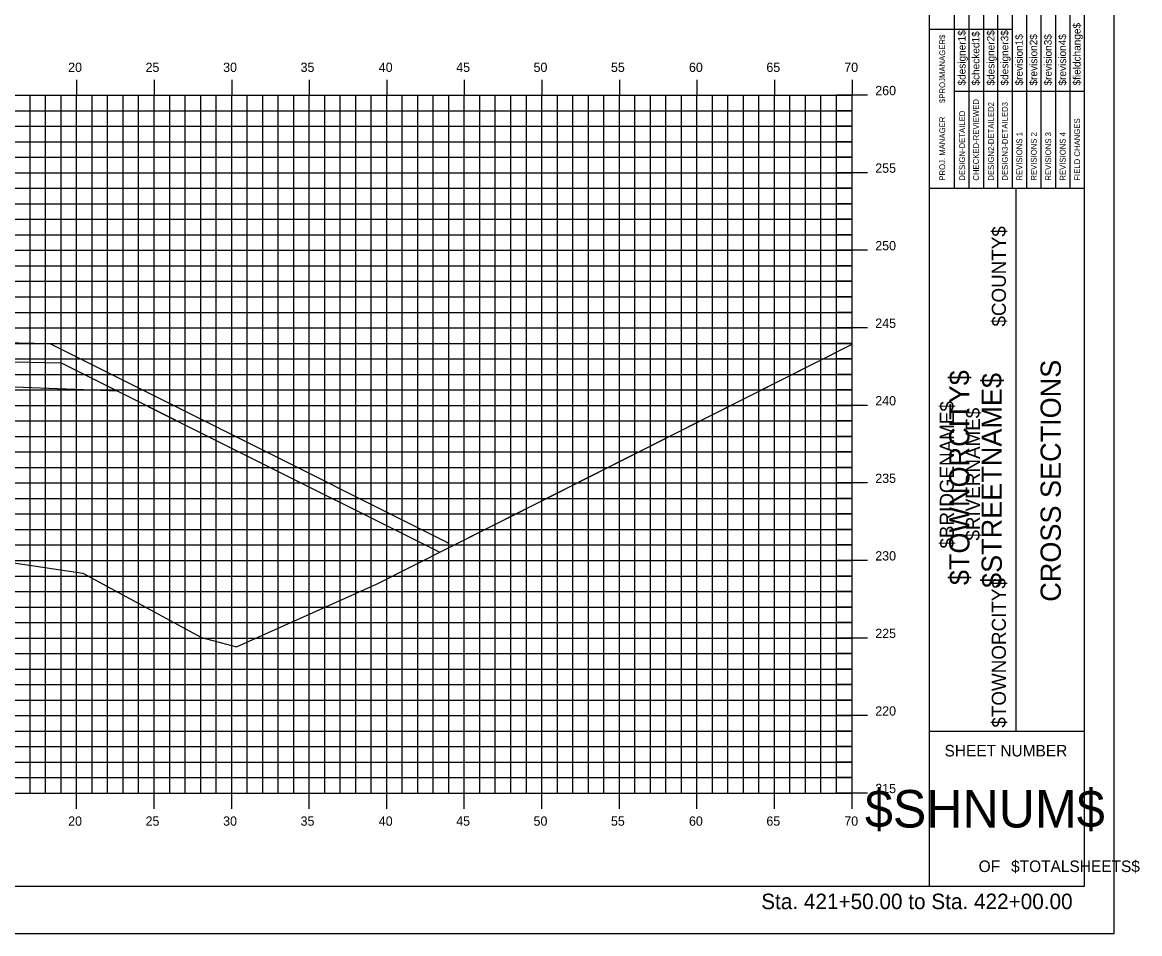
# Model space of a CAD drawing. Extents: x 1168600 to 1177589, y 610178 to 611246.
# Drawn here: x 1174314.9 to 1174386.9, y 610900.5 to 610959.3 of the extents above; entities that cross this region are included whole.
import ezdxf

# ---------------------------------------------------------------- set-up
doc = ezdxf.new("R2010")
doc.units = 0
for name, color, linetype in [('_Construction', 7, 'Continuous'), ('_Station Equation', 7, 'Continuous'), ('D_Roadway_SubGrade', 7, 'Continuous'), ('D_Slope_Direction', 7, 'Continuous'), ('D_Text_Standard', 7, 'Continuous'), ('H_V ANNOTATION', 7, 'Continuous'), ('MAJOR', 7, 'Continuous'), ('MINOR', 7, 'Continuous')]:
    doc.layers.add(name, color=color, linetype=linetype)

msp = doc.modelspace()

# ---------------------------------------------------------------- linework, layer by layer
at = {"layer": '_Construction'}
for p, q in [((1174373.367, 610903.599), (1174373.367, 611008.599)), ((1174383.367, 610903.599), (1174383.367, 611008.599)), ((1174373.367, 610948.599), (1174383.367, 610948.599)), ((1174378.958, 610913.599), (1174378.958, 610948.599)), ((1174373.367, 610913.599), (1174383.367, 610913.599)), ((1174223.367, 610903.596), (1174383.367, 610903.596))]:
    msp.add_line(p, q, dxfattribs=at)
msp.add_lwpolyline([(1174215.274, 610900.537), (1174385.274, 610900.537), (1174385.274, 611010.537), (1174215.274, 611010.537)], close=True, dxfattribs=at)
for points in [[(1174375.915, 610948.602), (1174375.915, 610966.099)], [(1174376.846, 610966.099), (1174376.846, 610948.602)], [(1174377.778, 610948.602), (1174377.778, 610966.099)], [(1174378.71, 610948.602), (1174378.71, 610966.099)], [(1174379.641, 610948.602), (1174379.641, 610966.099)], [(1174380.573, 610948.602), (1174380.573, 610966.099)], [(1174381.505, 610948.602), (1174381.505, 610966.099)], [(1174382.437, 610948.602), (1174382.437, 610966.099)], [(1174374.983, 610948.602), (1174374.983, 610965.393)], [(1174373.367, 610958.849), (1174374.983, 610958.849)], [(1174374.982, 610958.849), (1174378.709, 610958.849)], [(1174374.982, 610954.849), (1174383.367, 610954.849)]]:
    msp.add_lwpolyline(points, dxfattribs=at)
at = {"layer": '_Station Equation'}
for points in [[(1174228.367, 610948.347), (1174246.198, 610940.577), (1174261.693, 610933.725), (1174264.668, 610933.087), (1174297.116, 610927.92), (1174312.267, 610924.748), (1174318.764, 610923.769), (1174326.425, 610919.637), (1174328.67, 610919.022), (1174337.751, 610923.098), (1174368.367, 610938.545)], [(1174313.66, 610938.66), (1174316.63, 610938.598), (1174319.27, 610937.276), (1174319.309, 610937.257), (1174327.558, 610933.126), (1174327.716, 610933.047), (1174327.778, 610933.016), (1174342.333, 610925.727), (1174342.336, 610925.696), (1174342.337, 610925.757), (1174342.337, 610925.784), (1174342.341, 610925.413), (1174342.341, 610925.414), (1174342.381, 610925.434), (1174342.384, 610925.436), (1174348.791, 610928.668), (1174368.367, 610938.545)]]:
    msp.add_lwpolyline(points, dxfattribs=at)
at = {"layer": 'D_Roadway_SubGrade'}
msp.add_lwpolyline([(1174314.367, 610937.396), (1174317.367, 610937.336), (1174321.03, 610935.504), (1174314.367, 610935.771)], close=True, dxfattribs=at)
at = {"layer": 'D_Slope_Direction'}
for points in [[(1174317.367, 610937.336), (1174328.45, 610931.794)], [(1174328.45, 610931.794), (1174341.778, 610925.13)]]:
    msp.add_lwpolyline(points, dxfattribs=at)
at = {"layer": 'D_Text_Standard'}
msp.add_lwpolyline([(1174267.429, 610932.647), (1174268.284, 610933.074), (1174276.691, 610937.278), (1174279.367, 610938.616), (1174282.367, 610938.676), (1174298.367, 610938.036), (1174314.367, 610937.396), (1174317.367, 610937.336), (1174321.03, 610935.504), (1174328.45, 610931.794), (1174341.778, 610925.13)], dxfattribs=at)
at = {"layer": 'MAJOR'}
for p, q in [((1174318.367, 610955.598), (1174318.367, 610954.596)), ((1174323.367, 610955.598), (1174323.367, 610954.596)), ((1174328.367, 610955.598), (1174328.367, 610954.596)), ((1174333.367, 610955.598), (1174333.367, 610954.596)), ((1174338.367, 610955.598), (1174338.367, 610954.596)), ((1174343.367, 610955.598), (1174343.367, 610954.596)), ((1174348.367, 610955.598), (1174348.367, 610954.596)), ((1174353.367, 610955.598), (1174353.367, 610954.596)), ((1174358.367, 610955.598), (1174358.367, 610954.596)), ((1174363.367, 610955.598), (1174363.367, 610954.596)), ((1174368.367, 610955.598), (1174368.367, 610954.596)), ((1174228.367, 610954.596), (1174368.367, 610954.596)), ((1174228.367, 610954.596), (1174368.367, 610954.596)), ((1174318.367, 610909.596), (1174318.367, 610954.596)), ((1174323.367, 610909.596), (1174323.367, 610954.596)), ((1174328.367, 610909.596), (1174328.367, 610954.596)), ((1174333.367, 610909.596), (1174333.367, 610954.596)), ((1174338.367, 610909.596), (1174338.367, 610954.596)), ((1174343.367, 610909.596), (1174343.367, 610954.596)), ((1174348.367, 610909.596), (1174348.367, 610954.596)), ((1174353.367, 610909.596), (1174353.367, 610954.596)), ((1174358.367, 610909.596), (1174358.367, 610954.596)), ((1174363.367, 610909.596), (1174363.367, 610954.596)), ((1174369.369, 610954.596), (1174367.365, 610954.596)), ((1174368.367, 610909.596), (1174368.367, 610954.596)), ((1174368.367, 610909.596), (1174368.367, 610954.596)), ((1174228.367, 610949.596), (1174368.367, 610949.596)), ((1174369.369, 610949.596), (1174367.365, 610949.596)), ((1174228.367, 610944.596), (1174368.367, 610944.596)), ((1174369.369, 610944.596), (1174367.365, 610944.596)), ((1174228.367, 610939.596), (1174368.367, 610939.596)), ((1174369.369, 610939.596), (1174367.365, 610939.596)), ((1174228.367, 610934.596), (1174368.367, 610934.596)), ((1174369.369, 610934.596), (1174367.365, 610934.596)), ((1174228.367, 610929.596), (1174368.367, 610929.596)), ((1174369.369, 610929.596), (1174367.365, 610929.596)), ((1174228.367, 610924.596), (1174368.367, 610924.596)), ((1174369.369, 610924.596), (1174367.365, 610924.596)), ((1174228.367, 610919.596), (1174368.367, 610919.596)), ((1174369.369, 610919.596), (1174367.365, 610919.596)), ((1174228.367, 610914.596), (1174368.367, 610914.596)), ((1174369.369, 610914.596), (1174367.365, 610914.596)), ((1174228.367, 610909.596), (1174368.367, 610909.596)), ((1174228.367, 610909.596), (1174368.367, 610909.596)), ((1174318.367, 610908.594), (1174318.367, 610909.596)), ((1174323.367, 610908.594), (1174323.367, 610909.596)), ((1174328.367, 610908.594), (1174328.367, 610909.596)), ((1174333.367, 610908.594), (1174333.367, 610909.596)), ((1174338.367, 610908.594), (1174338.367, 610909.596)), ((1174343.367, 610908.594), (1174343.367, 610909.596)), ((1174348.367, 610908.594), (1174348.367, 610909.596)), ((1174353.367, 610908.594), (1174353.367, 610909.596)), ((1174358.367, 610908.594), (1174358.367, 610909.596)), ((1174363.367, 610908.594), (1174363.367, 610909.596)), ((1174369.369, 610909.596), (1174367.365, 610909.596)), ((1174368.367, 610908.594), (1174368.367, 610909.596))]:
    msp.add_line(p, q, dxfattribs=at)
at = {"layer": 'MINOR'}
for p, q in [((1174315.367, 610909.596), (1174315.367, 610954.596)), ((1174316.367, 610909.596), (1174316.367, 610954.596)), ((1174317.367, 610909.596), (1174317.367, 610954.596)), ((1174319.367, 610909.596), (1174319.367, 610954.596)), ((1174320.367, 610909.596), (1174320.367, 610954.596)), ((1174321.367, 610909.596), (1174321.367, 610954.596)), ((1174322.367, 610909.596), (1174322.367, 610954.596)), ((1174324.367, 610909.596), (1174324.367, 610954.596)), ((1174325.367, 610909.596), (1174325.367, 610954.596)), ((1174326.367, 610909.596), (1174326.367, 610954.596)), ((1174327.367, 610909.596), (1174327.367, 610954.596)), ((1174329.367, 610909.596), (1174329.367, 610954.596)), ((1174330.367, 610909.596), (1174330.367, 610954.596)), ((1174331.367, 610909.596), (1174331.367, 610954.596)), ((1174332.367, 610909.596), (1174332.367, 610954.596)), ((1174334.367, 610909.596), (1174334.367, 610954.596)), ((1174335.367, 610909.596), (1174335.367, 610954.596)), ((1174336.367, 610909.596), (1174336.367, 610954.596)), ((1174337.367, 610909.596), (1174337.367, 610954.596)), ((1174339.367, 610909.596), (1174339.367, 610954.596)), ((1174340.367, 610909.596), (1174340.367, 610954.596)), ((1174341.367, 610909.596), (1174341.367, 610954.596)), ((1174342.367, 610909.596), (1174342.367, 610954.596)), ((1174344.367, 610909.596), (1174344.367, 610954.596)), ((1174345.367, 610909.596), (1174345.367, 610954.596)), ((1174346.367, 610909.596), (1174346.367, 610954.596)), ((1174347.367, 610909.596), (1174347.367, 610954.596)), ((1174349.367, 610909.596), (1174349.367, 610954.596)), ((1174350.367, 610909.596), (1174350.367, 610954.596)), ((1174351.367, 610909.596), (1174351.367, 610954.596)), ((1174352.367, 610909.596), (1174352.367, 610954.596)), ((1174354.367, 610909.596), (1174354.367, 610954.596)), ((1174355.367, 610909.596), (1174355.367, 610954.596)), ((1174356.367, 610909.596), (1174356.367, 610954.596)), ((1174357.367, 610909.596), (1174357.367, 610954.596)), ((1174359.367, 610909.596), (1174359.367, 610954.596)), ((1174360.367, 610909.596), (1174360.367, 610954.596)), ((1174361.367, 610909.596), (1174361.367, 610954.596)), ((1174362.367, 610909.596), (1174362.367, 610954.596)), ((1174364.367, 610909.596), (1174364.367, 610954.596)), ((1174365.367, 610909.596), (1174365.367, 610954.596)), ((1174366.367, 610909.596), (1174366.367, 610954.596)), ((1174367.367, 610909.596), (1174367.367, 610954.596)), ((1174228.367, 610953.596), (1174368.367, 610953.596)), ((1174368.367, 610953.596), (1174367.365, 610953.596)), ((1174228.367, 610952.596), (1174368.367, 610952.596)), ((1174368.367, 610952.596), (1174367.365, 610952.596)), ((1174228.367, 610951.596), (1174368.367, 610951.596)), ((1174368.367, 610951.596), (1174367.365, 610951.596)), ((1174228.367, 610950.596), (1174368.367, 610950.596)), ((1174368.367, 610950.596), (1174367.365, 610950.596)), ((1174228.367, 610948.596), (1174368.367, 610948.596)), ((1174368.367, 610948.596), (1174367.365, 610948.596)), ((1174228.367, 610947.596), (1174368.367, 610947.596)), ((1174368.367, 610947.596), (1174367.365, 610947.596)), ((1174228.367, 610946.596), (1174368.367, 610946.596)), ((1174368.367, 610946.596), (1174367.365, 610946.596)), ((1174228.367, 610945.596), (1174368.367, 610945.596)), ((1174368.367, 610945.596), (1174367.365, 610945.596)), ((1174228.367, 610943.596), (1174368.367, 610943.596)), ((1174368.367, 610943.596), (1174367.365, 610943.596)), ((1174228.367, 610942.596), (1174368.367, 610942.596)), ((1174368.367, 610942.596), (1174367.365, 610942.596)), ((1174228.367, 610941.596), (1174368.367, 610941.596)), ((1174368.367, 610941.596), (1174367.365, 610941.596)), ((1174228.367, 610940.596), (1174368.367, 610940.596)), ((1174368.367, 610940.596), (1174367.365, 610940.596)), ((1174228.367, 610938.596), (1174368.367, 610938.596)), ((1174368.367, 610938.596), (1174367.365, 610938.596)), ((1174228.367, 610937.596), (1174368.367, 610937.596)), ((1174368.367, 610937.596), (1174367.365, 610937.596)), ((1174228.367, 610936.596), (1174368.367, 610936.596)), ((1174368.367, 610936.596), (1174367.365, 610936.596)), ((1174228.367, 610935.596), (1174368.367, 610935.596)), ((1174368.367, 610935.596), (1174367.365, 610935.596)), ((1174228.367, 610933.596), (1174368.367, 610933.596)), ((1174368.367, 610933.596), (1174367.365, 610933.596)), ((1174228.367, 610932.596), (1174368.367, 610932.596)), ((1174368.367, 610932.596), (1174367.365, 610932.596)), ((1174228.367, 610931.596), (1174368.367, 610931.596)), ((1174368.367, 610931.596), (1174367.365, 610931.596)), ((1174228.367, 610930.596), (1174368.367, 610930.596)), ((1174368.367, 610930.596), (1174367.365, 610930.596)), ((1174228.367, 610928.596), (1174368.367, 610928.596)), ((1174368.367, 610928.596), (1174367.365, 610928.596)), ((1174228.367, 610927.596), (1174368.367, 610927.596)), ((1174368.367, 610927.596), (1174367.365, 610927.596)), ((1174228.367, 610926.596), (1174368.367, 610926.596)), ((1174368.367, 610926.596), (1174367.365, 610926.596)), ((1174228.367, 610925.596), (1174368.367, 610925.596)), ((1174368.367, 610925.596), (1174367.365, 610925.596)), ((1174228.367, 610923.596), (1174368.367, 610923.596)), ((1174368.367, 610923.596), (1174367.365, 610923.596)), ((1174228.367, 610922.596), (1174368.367, 610922.596)), ((1174368.367, 610922.596), (1174367.365, 610922.596)), ((1174228.367, 610921.596), (1174368.367, 610921.596)), ((1174368.367, 610921.596), (1174367.365, 610921.596)), ((1174228.367, 610920.596), (1174368.367, 610920.596)), ((1174368.367, 610920.596), (1174367.365, 610920.596)), ((1174228.367, 610918.596), (1174368.367, 610918.596)), ((1174368.367, 610918.596), (1174367.365, 610918.596)), ((1174228.367, 610917.596), (1174368.367, 610917.596)), ((1174368.367, 610917.596), (1174367.365, 610917.596)), ((1174228.367, 610916.596), (1174368.367, 610916.596)), ((1174368.367, 610916.596), (1174367.365, 610916.596)), ((1174228.367, 610915.596), (1174368.367, 610915.596)), ((1174368.367, 610915.596), (1174367.365, 610915.596)), ((1174228.367, 610913.596), (1174368.367, 610913.596)), ((1174368.367, 610913.596), (1174367.365, 610913.596)), ((1174228.367, 610912.596), (1174368.367, 610912.596)), ((1174368.367, 610912.596), (1174367.365, 610912.596)), ((1174228.367, 610911.596), (1174368.367, 610911.596)), ((1174368.367, 610911.596), (1174367.365, 610911.596)), ((1174228.367, 610910.596), (1174368.367, 610910.596)), ((1174368.367, 610910.596), (1174367.365, 610910.596))]:
    msp.add_line(p, q, dxfattribs=at)

# ---------------------------------------------------------------- texts
at = {"layer": '_Construction'}
for s, height, rotation, p in [('$fieldchange$', 0.48455, 90, (1174383.106, 610955.222)), ('$PROJMANAGER$', 0.37275, 90, (1174374.372, 610954.094)), ('$designer1$', 0.48455, 90, (1174375.69, 610955.222)), ('$checked1$', 0.4845, 90, (1174376.585, 610955.222)), ('$designer2$', 0.48455, 90, (1174377.554, 610955.222)), ('$designer3$', 0.48455, 90, (1174378.448, 610955.222)), ('$revision1$', 0.48455, 90, (1174379.38, 610955.222)), ('$revision2$', 0.48455, 90, (1174380.311, 610955.222)), ('$revision3$', 0.48455, 90, (1174381.243, 610955.222)), ('$revision4$', 0.48455, 90, (1174382.175, 610955.222)), ('CHECKED-REVIEWED', 0.37275, 90, (1174376.548, 610949.087)), ('DESIGN2-DETAILED2', 0.37275, 90, (1174377.517, 610949.087)), ('DESIGN3-DETAILED3', 0.37275, 90, (1174378.412, 610949.087)), ('DESIGN-DETAILED', 0.37275, 90, (1174375.654, 610949.087)), ('PROJ. MANAGER', 0.37275, 90, (1174374.372, 610949.087)), ('FIELD CHANGES', 0.37275, 90, (1174383.07, 610949.087)), ('REVISIONS 1', 0.37275, 90, (1174379.343, 610949.087)), ('REVISIONS 2', 0.37275, 90, (1174380.275, 610949.087)), ('REVISIONS 3', 0.37275, 90, (1174381.207, 610949.087)), ('REVISIONS 4', 0.37275, 90, (1174382.138, 610949.087)), ('$COUNTY$', 0.9072, 90, (1174378.288, 610939.678)), ('CROSS SECTIONS', 1.30428, 90, (1174381.832, 610921.938)), ('$TOWNORCITY$', 1.30428, 90, (1174375.94, 610923.007)), ('$STREETNAME$', 1.30428, 90, (1174378.027, 610922.827)), ('$BRIDGENAME$', 0.90716, 90, (1174374.933, 610925.367)), ('$RIVERNAME$', 0.90716, 90, (1174376.61, 610925.882)), ('$TOWNORCITY$', 0.90716, 90, (1174378.288, 610913.82)), ('SHEET NUMBER', 0.74527, 360, (1174374.333, 610911.963)), ('$SHNUM$', 2.4194, 360, (1174369.201, 610907.379)), ('OF', 0.7453, 360, (1174376.534, 610904.509)), ('$TOTALSHEETS$', 0.74527, 360, (1174378.624, 610904.509))]:
    msp.add_text(s, height=height, rotation=rotation, dxfattribs=at).set_placement(p)
at = {"layer": 'H_V ANNOTATION'}
for s, height, p in [('20', 0.6, (1174317.821, 610956.096)), ('25', 0.6, (1174322.813, 610956.096)), ('30', 0.6, (1174327.816, 610956.096)), ('35', 0.6, (1174332.808, 610956.096)), ('40', 0.6, (1174337.853, 610956.096)), ('45', 0.6, (1174342.845, 610956.096)), ('50', 0.6, (1174347.832, 610956.096)), ('55', 0.6, (1174352.824, 610956.096)), ('60', 0.6, (1174357.853, 610956.096)), ('65', 0.6, (1174362.845, 610956.096)), ('70', 0.6, (1174367.869, 610956.096)), ('260', 0.6, (1174369.867, 610954.596)), ('255', 0.6, (1174369.867, 610949.596)), ('250', 0.6, (1174369.867, 610944.596)), ('245', 0.6, (1174369.867, 610939.596)), ('240', 0.6, (1174369.867, 610934.596)), ('235', 0.6, (1174369.867, 610929.596)), ('230', 0.6, (1174369.867, 610924.596)), ('225', 0.6, (1174369.867, 610919.596)), ('220', 0.6, (1174369.867, 610914.596)), ('215', 0.6, (1174369.867, 610909.596)), ('20', 0.6, (1174317.821, 610907.496)), ('25', 0.6, (1174322.813, 610907.496)), ('30', 0.6, (1174327.816, 610907.496)), ('35', 0.6, (1174332.808, 610907.496)), ('40', 0.6, (1174337.853, 610907.496)), ('45', 0.6, (1174342.845, 610907.496)), ('50', 0.6, (1174347.832, 610907.496)), ('55', 0.6, (1174352.824, 610907.496)), ('60', 0.6, (1174357.853, 610907.496)), ('65', 0.6, (1174362.845, 610907.496)), ('70', 0.6, (1174367.869, 610907.496)), ('Sta. 421+50.00 to Sta. 422+00.00', 1.0002, (1174362.513, 610902.116))]:
    msp.add_text(s, height=height, dxfattribs=at).set_placement(p)

doc.saveas('drawing.dxf')
